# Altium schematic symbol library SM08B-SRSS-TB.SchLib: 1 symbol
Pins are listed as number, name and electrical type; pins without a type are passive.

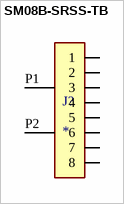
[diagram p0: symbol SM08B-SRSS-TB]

## SM08B-SRSS-TB
designator J?
SH Series 8 Position 1 mm Pitch Surface Mount Side Entry Shrouded Header; MF: {'manufacturer': u'JST Sales America Inc.'}; MP: SM08B-SRSS-TB
footprint JST_SM08B-SRSS-TB
pins: 1, 2, 3, 4, 5, 6, 7, 8, P1, P2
